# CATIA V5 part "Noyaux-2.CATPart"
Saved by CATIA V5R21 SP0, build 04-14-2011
Part number: Noyaux
Bounding box of the stored display mesh (mm): x -7.25 to 7.25, y -70.25 to 67.25, z -7.249 to 7.249
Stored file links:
  C:\Users\zerma\Pictures\Moule_2\Noyaux-2.CATPart
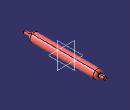
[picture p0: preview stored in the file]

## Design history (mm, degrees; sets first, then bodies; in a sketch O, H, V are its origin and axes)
Body1 (main body)
  DatumCurve1 "Longueur_moule"
  DatumCurve2
  DatumCurve3
  Sketch1 on yz-plane, origin (0, 0, 0), H (0, 1, 0), V (0, 0, 1)
    point P1 (58.25, 7.25)
    point P2 (0, 0)
    line L1 (67.25, 0) -> (67.25, 2.5)
    line L2 (67.25, 2.5) -> (58.25, 2.5)
    point P5 (58.25, 2.5)
    line L3 (58.25, 7.25) -> (58.25, 2.5)
    point P6 (-58.25, 7.25)
    line L4 (-58.25, 7.25) -> (58.25, 7.25)
    line L5 (67.25, 0) -> (-70.25, 0)
    point P8 (-58.25, 2.5)
    point P9 (-58.25, 7.25)
    line L6 (-58.25, 7.25) -> (-58.25, 2.5)
    line L7 (-70.25, 0) -> (-70.25, 2.5)
    line L8 (-58.25, 2.5) -> (-70.25, 2.5)
    length L2 = 9
    length L1 = 2.5
    length L4 = 116.5
    length L8 = 12
    distance L4 L5 = 7.25
    vertical: L1 V, L3 V, L7 V
    horizontal: L2 H, L4 H, L5 H, L8 H
    coincidence: P2 O, L5 H
    symmetry: P1 P6 V, P5 P8 V, P1 P9 V, L3 L6 V
  Shaft1: profile Sketch1, axis Sketch1.L5, angle 360
  Fillet1: radius 4, on edge [face of Shaft1 from Sketch1.L4 | face of Shaft1 from Sketch1.L3]; edge [face of Shaft1 from Sketch1.L6 | face of Shaft1 from Sketch1.L4]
